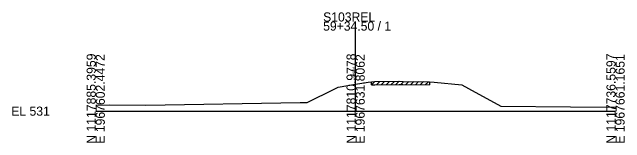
# Model space of a CAD drawing. Extents: x -26 to 163, y -10 to 24518.
# Drawn here: x -25.7 to 162.8, y 9990.3 to 10030.4 of the extents above; entities that cross this region are included whole.
import ezdxf

# ---------------------------------------------------------------- set-up
doc = ezdxf.new("R2010")
doc.units = 0
for name, color, linetype in [('RD_GPK_XS_Cell', 7, 'Continuous'), ('RD_XS_ExGround', 7, 'Continuous'), ('RD_XS_ExPaveRet', 7, 'Continuous'), ('RD_XS_TX_Elev_EX', 7, 'Continuous')]:
    doc.layers.add(name, color=color, linetype=linetype)

msp = doc.modelspace()

# ---------------------------------------------------------------- linework, layer by layer
at = {"layer": 'RD_GPK_XS_Cell'}
for p, q in [((80, 10000), (80, 10027.52)), ((0, 10000), (80, 10000)), ((80, 10000), (160, 10000))]:
    msp.add_line(p, q, dxfattribs=at)
at = {"layer": 'RD_XS_ExGround'}
msp.add_lwpolyline([(0, 10001.8), (4.28, 10001.89), (15.4, 10001.81), (62.94, 10002.61), (65.06, 10002.66), (73.6, 10006.9), (74.58, 10007.38), (80, 10008.26), (83.91, 10008.89), (84.91, 10009.05), (85.87, 10009.06), (93.43, 10009.17), (94.57, 10009.15), (102.76, 10009.04), (104.22, 10008.88), (112.71, 10008.09), (114.75, 10006.98), (124.66, 10001.56), (146.1, 10001.31), (160, 10001.22)], dxfattribs=at)
at = {"layer": 'RD_XS_ExPaveRet'}
for p, q in [((84.91, 10008.05), (85.92, 10009.06)), ((84.91, 10008.05), (84.91, 10009.05)), ((84.91, 10008.05), (85.87, 10008.06)), ((85.87, 10008.06), (93.43, 10008.17)), ((86.41, 10008.07), (87.42, 10009.09)), ((87.91, 10008.09), (88.92, 10009.11)), ((89.41, 10008.11), (90.42, 10009.13)), ((90.91, 10008.14), (91.92, 10009.15)), ((92.41, 10008.16), (93.42, 10009.17)), ((93.43, 10008.17), (94.57, 10008.15)), ((93.91, 10008.16), (94.89, 10009.15)), ((94.57, 10008.15), (102.76, 10008.04)), ((95.41, 10008.14), (96.39, 10009.13)), ((96.91, 10008.12), (97.89, 10009.11)), ((98.41, 10008.1), (99.39, 10009.08)), ((99.91, 10008.08), (100.89, 10009.06)), ((101.41, 10008.06), (102.39, 10009.04)), ((102.76, 10009.04), (102.76, 10008.04))]:
    msp.add_line(p, q, dxfattribs=at)

# ---------------------------------------------------------------- texts
at = {"layer": 'RD_GPK_XS_Cell'}
for s, p in [('S103REL', (70, 10027.52)), ('59+34.50 / 1', (70, 10024.72)), ('EL 531', (-26, 9998.6))]:
    msp.add_text(s, height=2.8, dxfattribs=at).set_placement(p)
for s, p in [('N 1117885.3959', (0, 9990)), ('E 1967602.4472', (2.8, 9990)), ('N 1117810.9778', (80, 9990)), ('E 1967631.8062', (82.8, 9990)), ('N 1117736.5597', (160, 9990)), ('E 1967661.1651', (162.8, 9990))]:
    msp.add_text(s, height=2.8, rotation=90, dxfattribs=at).set_placement(p)
at = {"layer": 'RD_XS_TX_Elev_EX'}
msp.add_text('539.26', height=0.8, rotation=90, dxfattribs=at).set_placement((79.9, 10010.26))

doc.saveas('drawing.dxf')
